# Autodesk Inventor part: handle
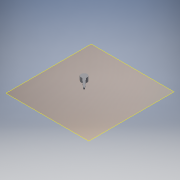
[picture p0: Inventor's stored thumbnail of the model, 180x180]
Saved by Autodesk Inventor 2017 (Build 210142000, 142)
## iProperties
Created: 2017-05
Part Number: handle
Material: Generic
Document SubType Name: Modeling
Designer: 1717440
Density: 1 g/cm^3
Appearance: Default
Author: 1717440
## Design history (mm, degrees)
workplane "Work Plane1"
sketch "Sketch1"
  geometry: C1 r 3.386 at (28.282, 83.089) reference; C2 r 3.486 at (28.282, 83.089); C3 r 5.613 at (28.282, 83.089); 1 further point
  constraints: 3 centre point, 1 coincident, 2 other
  dimensions: "d0" = 0.1 radial gap between concentric circles of C1 C2
workplane "Work Plane2"
extrude "Extrusion1" new body sketch "Sketch1" stored distance "d1" = 10; taper "d2" = 0 deg
sketch "Sketch2"
  geometry: C1 r 5.613 at (0, 0) reference; C2 r 5.613 at (0, 0); 1 further point
  constraints: 1 centre point, 1 coincident, 1 concentric
extrude "Extrusion2" join sketch "Sketch2" distance "d3" = 3; taper "d4" = 0 deg
sketch "Sketch3"
  geometry: L1 (0, 0)-(21, -21); L2 (21.601, -20.399)-(21, -21); L3 (21.601, -20.399)-(2, 2); L4 (20.399, -21.601)-(21, -21); L5 (20.399, -21.601)-(-2, -2); L6 (2, 2)-(-2, -2); C1 r 5.613 at (0, 0) reference; 1 further point
  constraints: 12 end point, 2 symmetric about line
extrude "Extrusion3" join sketch "Sketch3" distance "d5" = 2.5; taper "d6" = 0 deg
sketch "Sketch4"
  geometry: L1 (-1.431, -0.671)-(-2.771, -1.946) reference; L2 (-2.082, -2.67)-(-0.742, -1.396) reference; L3 (-0.742, -1.396)-(-1.431, -0.671) reference; L4 (-0.742, -1.396)-(-2.155, -2.74); L5 (-0.742, -1.396)-(-1.431, -0.671); L6 (-1.431, -0.671)-(-3.206, -2.359); L7 (-0.742, -1.396)-(-2.517, -3.084); L8 (-2.517, -3.084)-(-3.206, -2.359); L9 (-0.884, -1.393)-(-2.234, -2.677); L10 (-2.785, -2.097)-(-1.435, -0.813); L11 (-1.435, -0.813)-(-0.884, -1.393); A1 r 3.386 centre (0, 0) between (-2.082, -2.67) and (-2.771, -1.946) reference; A2 r 3.486 centre (0, 0) between (-2.234, -2.677) and (-2.785, -2.097); 2 further points
  constraints: 16 end point, 3 point on line, 2 point on circle, 1 centre point, 1 collinear, 1 perpendicular, 5 other
  dimensions: "d7" = 0.1 distance between parallel lines of L2 L9
extrude "Extrusion4" join sketch "Sketch4" stored distance "d8" = 2.5; taper "d9" = 0 deg
sketch "Sketch5"
  geometry: L1 (-3.344, 2.5)-(-1.7, 2.5) reference; L2 (-2.522, 2.5)-(0.769, 2.5); L3 (0.769, 2.5)-(0.769, -0.577); L4 (0.769, -0.577)-(-2.522, -0.577); L5 (-2.522, -0.577)-(-2.522, 2.5); 1 further point
  constraints: 8 end point, 2 parallel, 1 horizontal, 1 midpoint, 1 perpendicular
extrude "Extrusion5" cut sketch "Sketch5" distance "d10" = 3; taper "d11" = 0 deg
body "Solid1"
node "Reference1"
